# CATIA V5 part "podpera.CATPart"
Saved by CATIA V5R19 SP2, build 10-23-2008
Part number: podpera
Material "Steel": density 7860 kg/m3, Young's modulus 2e+11 Pa, Poisson ratio 0.266, thermal expansion 1.17e-05 1/K
Bounding box of the stored display mesh (mm): x -10 to 10, y -20 to 20, z 0 to 21
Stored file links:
  D:\Prace\Catia\nosnik1\podpera.CATPart
  C:\Program Files\Dassault Systemes\B19\intel_a\startup\materials\Catalog.CATMaterial
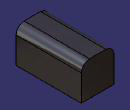
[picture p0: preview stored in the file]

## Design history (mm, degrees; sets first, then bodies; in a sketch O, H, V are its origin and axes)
AxisSystem1: origin (0, 0, 0), X (1, 0, 0), Y (0, 1, 0), Z (0, 0, 1)
Body1 (main body)
  Sketch1 on XY plane of AxisSystem1, origin (0, 0, 0), H (1, 0, 0), V (0, 1, 0)
    line L1 (10, 20) -> (10, -20)
    line L2 (10, -20) -> (-10, -20)
    line L3 (-10, -20) -> (-10, 20)
    line L4 (-10, 20) -> (10, 20)
    distance L2 L4 = 40
    distance L1 L3 = 20
    vertical: L1 V, L3 V
    horizontal: L2 H, L4 H
    equidistance: L1 L3 O, L2 L4 O
  Pad1: profile Sketch1, direction (0, 0, 1), length 21
  Fillet1: radius 5, on edge [face of Pad1 from Sketch1.L1 | end face of Pad1]; edge [face of Pad1 from Sketch1.L3 | end face of Pad1]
